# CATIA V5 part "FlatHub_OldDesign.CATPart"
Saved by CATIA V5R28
Part number: FlatHub_OldDesign
Material "Aluminium": density 2710 kg/m3, Young's modulus 7e+10 Pa, Poisson ratio 0.346, thermal expansion 2.36e-05 1/K
Bounding box of the stored display mesh (mm): x -147.037 to 147.037, y -84.892 to 169.784, z -80 to 0
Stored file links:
  H:\Maskiningenjör\Examensarbete\Klart\Klart & Skickas\FlatHub_OldDesign.CATPart
  H:\Maskiningenjör\Examensarbete\Klart\Stativ o allt\Undersida_Nav_3_alt3.CATPart
  H:\Examensarbete\Catia filer\BestNavDesigns\Nav1.3_Klar.CATPart
  H:\Maskiningenjör\Examensarbete\Klart\Klart & Skickas\AssemblyBlad_OriginalDesign.CATProduct
  H:\Maskiningenjör\Examensarbete\Klart\Klart & Skickas\HJALPMEDEL.CATPart
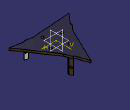
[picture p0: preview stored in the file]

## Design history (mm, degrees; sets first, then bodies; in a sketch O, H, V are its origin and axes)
Set1
  DatumPoint1 to DatumPoint4: linked copy from another document
Set2 "Design4_OriginalDesign"
  Set3 "PartUnderHub /Fills+Sketches+Extrudes+Trim"
    Set4 "Extrudes"
      Extrude1 "Extrude.ForUndersida": Element1 Sketch1, Lim1 20, Lim2 0, Direction (0, 0, 1), FirstUpto xy-plane
      Extrude2 "Extrude.SketchForLegs": Element1 Sketch3, Lim1 70, Lim2 0
      Extrude3 "Extrude.InnerMiddleTriangle": Element1 Sketch2, Lim1 30, Lim2 0
    Set5 "Fills"
      Fill1 "UnderFill": Boundary Sketch1
      Fill2 "Fill.UnderLeg1": Boundary (edge of Extrude2; edge of Extrude2; edge of Extrude2; edge of Extrude2; edge of Extrude2)
      Fill3 "Fill.UnderLeg2": Boundary (edge of Extrude2; edge of Extrude2; edge of Extrude2; edge of Extrude2; edge of Extrude2)
      Fill4 "Fill.UnderLeg3": Boundary (edge of Extrude2; edge of Extrude2; edge of Extrude2; edge of Extrude2; edge of Extrude2)
      Fill5 "Fill.UnderMiddleTriangle": Boundary (edge of Extrude3; edge of Extrude3; edge of Extrude3)
      Fill6 "TopOfUndersida.Fill": Boundary (edge of Extrude1; edge of Extrude1; edge of Extrude1; edge of Extrude1; edge of Extrude1; edge of Extrude1; edge of Extrude1; edge of Extrude1; edge of Extrude1; edge of Extrude1; edge of Extrude1; edge of Extrude1)
    Set6 "Trims"
      Trim1: Trimmed (Fill1; Extrude2)
      Trim2: Trimmed (Trim1; Extrude3)
    Set7 "JoinedUndersida"
      Join1 "Join.Undersida": Elements (Trim2; Extrude1; Fill2; Fill3; Fill4; Fill5; Fill6)
    Set8 "Sketches"
      Sketch1 "SketchForUnderSida" on Plane1, origin (0, 0, -10), H (1, 0, 0), V (0, 1, 0)
        construction line L1 (21.7487, 107.4703) -> (27.6798, 90.4756)
        construction line L2 (-103.9464, -34.9002) -> (-92.194, -21.2664)
        construction line L3 (82.1977, -72.5701) -> (64.5142, -69.2092)
        construction line L4 (-155.7574, -1.82) -> (-42.4451, -36.4864)
        construction line L5 (60.4543, -51.6084) -> (73.7984, -109.458)
        point P1 (-92.194, -21.2664)
        point P2 (27.6798, 90.4756)
        point P3 (64.5142, -69.2092)
        point P4 (0, 0)
        point P5 (21.7487, 107.4703)
        point P6 (-103.9464, -34.9002)
        point P7 (82.1977, -72.5701)
        construction line L6 (27.6798, 90.4756) -> (-92.194, -21.2664)
        construction line L7 (-92.194, -21.2664) -> (64.5142, -69.2092)
        construction line L8 (64.5142, -69.2092) -> (27.6798, 90.4756)
        construction circle A1 centre (0, 0) radius 47.3075
        line L9 (-107.7337, -31.6358) -> (-103.9464, -34.9002)
        line L10 (82.1977, -72.5701) -> (81.2642, -77.4822)
        line L11 (21.7487, 107.4703) -> (26.4695, 109.118)
        construction line L12 (27.6798, 90.4756) -> (38.5506, 74.5035)
        point P16 (147.0373, -84.892)
        line L13 (147.0373, -84.892) -> (82.1977, -72.5701)
        construction line L14 (64.5142, -69.2092) -> (45.2466, -70.6376)
        point P17 (-147.0373, -84.892)
        line L15 (-147.0373, -84.892) -> (-103.9464, -34.9002)
        line L16 (-83.7972, -3.8659) -> (0, 169.784)
        point P18 (0, 169.784)
        line L17 (0, 169.784) -> (21.7487, 107.4703)
        point P20 (-103.9464, -34.9002)
        construction line L18 (-83.7972, -3.8659) -> (-92.194, -21.2664)
        line L19 (45.2466, -70.6376) -> (-147.0373, -84.892)
        point P22 (82.1977, -72.5701)
        construction line L20 (82.1977, -72.5701) -> (64.5142, -69.2092)
        line L21 (38.5506, 74.5035) -> (147.0373, -84.892)
        point P24 (21.7487, 107.4703)
        construction line L22 (21.7487, 107.4703) -> (27.6798, 90.4756)
        point P25 (13.4514, 15.6056)
        construction line L23 (13.4514, 15.6056) -> (-20.2405, 3.8464)
        point P26 (-20.2405, 3.8464)
        construction line L24 (-20.2405, 3.8464) -> (6.7891, -19.452)
        point P27 (6.7891, -19.452)
        construction line L25 (6.7891, -19.452) -> (13.4514, 15.6056)
        construction circle A2 centre (0, 0) radius 10.3014
        construction line L26 (-92.194, -21.2664) -> (-100.3085, 31.9728)
        construction line L27 (27.6798, 90.4756) -> (71.7562, 73.2608)
        construction line L28 (64.5142, -69.2092) -> (30.3334, -96.56)
        line L29 (81.2642, -77.4822) -> (45.2466, -70.6376)
        line L30 (26.4695, 109.118) -> (38.5506, 74.5035)
        line L31 (-83.7972, -3.8659) -> (-107.7337, -31.6358)
        reference intersected line E1 through (0, 0) direction (0, 1) from yz-plane
        length L2 = 18
        length L3 = 18
        length L1 = 18
        length L25 = 35.685
        length L23 = 35.685
        length L24 = 35.685
        length L26 = 53.854
        length L27 = 47.3189
        length L28 = 43.7767
        distance P2 P25 = 76.21
        distance P26 P1 = 76.21
        distance P27 P3 = 76.21
        angle L27 L25 = 79.426
        angle L28 L13 = 130.574
        angle L26 L23 = 79.426
        angle L27 L17 = 130.574
        angle L16 L15 = 165.0003 (reference)
        angle L26 L15 = 130.574
        angle L28 L24 = 79.426
        angle L13 L19 = 165.0003 (reference)
        angle L17 L21 = 165.0003 (reference)
        distance L13 L29 = 5
        distance L17 L30 = 5
        angle L10 L13 = 90
        angle L9 L15 = 90
        distance L31 L15 = 5
        angle L17 L11 = 90
        length L8 = 163.878
        length L6 = 163.878 (reference)
        length L7 = 163.878 (reference)
        distance P17 P1 = 84
        distance P3 P16 = 84
        distance P18 P2 = 84
        distance P17 P3 = 212.132
        distance P2 P16 = 212.132
        distance P1 P18 = 212.132
        tangency: A1 L8, A1 L6, A1 L7, L4 L7, A2 L25, A2 L23, A2 L24
        coincidence: L5 L8, L14 L19, P20 P6, L21 L12, P24 P5, P7 P22, P18 E1
        parallelism: L18 L16
        concentricity: A2 O, A1 O
      Sketch2 "InnerMiddleTriangle" on Plane1, origin (0, 0, -10), H (1, 0, 0), V (0, 1, 0)
        point P1 (13.681, 15.4046)
        construction line L1 (13.681, 15.4046) -> (-20.1813, 4.1458)
        point P2 (-20.1813, 4.1458)
        construction line L2 (-20.1813, 4.1458) -> (6.5003, -19.5504)
        point P3 (6.5003, -19.5504)
        construction line L3 (6.5003, -19.5504) -> (13.681, 15.4046)
        construction circle A1 centre (0, 0) radius 10.3014
        line L4 (7.9685, 8.9724) -> (-11.7545, 2.4147)
        line L5 (-11.7545, 2.4147) -> (3.7861, -11.3871)
        line L6 (3.7861, -11.3871) -> (7.9685, 8.9724)
        construction circle A2 centre (0, 0) radius 6
        point P7 (27.6798, 90.4756)
        construction line L7 (27.6798, 90.4756) -> (-92.194, -21.2664)
        point P8 (-92.194, -21.2664)
        construction line L8 (-92.194, -21.2664) -> (64.5142, -69.2092)
        point P9 (64.5142, -69.2092)
        construction line L9 (64.5142, -69.2092) -> (27.6798, 90.4756)
        construction line L10 (27.6798, 90.4756) -> (0, 169.784)
        point P10 (0, 169.784)
        construction line L11 (0, 169.784) -> (-92.194, -21.2664)
        construction line L12 (-92.194, -21.2664) -> (-147.0373, -84.892)
        construction line L13 (-147.0373, -84.892) -> (64.5142, -69.2092)
        construction line L14 (64.5142, -69.2092) -> (147.0373, -84.892)
        construction line L15 (147.0373, -84.892) -> (27.6798, 90.4756)
        reference intersected line E1 through (0, 0) direction (0, 1) from yz-plane
        construction circle A3 centre (0, 0) radius 47.3075
        point P13 (0, 0)
        length L3 = 35.685
        length L1 = 35.685
        length L2 = 35.685
        radius A2 = 6
        distance L6 L3 = 4.3014 (reference)
        length L9 = 163.878
        length L7 = 163.878
        length L8 = 163.878
        length L15 = 212.132
        length L14 = 84
        length L13 = 212.132
        length L12 = 84
        length L11 = 212.132
        length L10 = 84
        distance P1 P7 = 76.365
        distance P9 P3 = 76.365 (reference)
        distance P2 P8 = 76.365 (reference)
        angle L10 L15 = 165 (reference)
        angle L11 L12 = 165 (reference)
        angle L13 L14 = 165 (reference)
        tangency: A1 L3, A1 L1, A1 L2, A2 L4, A2 L6, A2 L5, A3 L8, A3 L9, A3 L7
        parallelism: L4 L1, L2 L5
        coincidence: P10 E1, P13 O
      Sketch3 "SketchForLegs" on Plane1, origin (0, 0, -10), H (1, 0, 0), V (0, 1, 0)
        construction line L1 (27.6798, 90.4756) -> (42.5834, 84.6546)
        construction line L2 (21.7484, 107.4702) -> (27.6798, 90.4756)
        construction line L3 (23.7707, 86.8317) -> (80.6201, 139.8245)
        construction line L4 (-103.9462, -34.9004) -> (-92.194, -21.2664)
        construction line L5 (-92.194, -21.2664) -> (-94.6047, -5.449)
        construction line L6 (82.1977, -72.5698) -> (64.5142, -69.2092)
        construction line L7 (64.5142, -69.2092) -> (52.0214, -79.2056)
        construction line L8 (-143.1451, -5.6786) -> (-29.8328, -40.345)
        construction line L9 (50.8896, -10.1436) -> (64.2338, -67.9933)
        point P3 (65.0054, -71.3383)
        point P5 (-94.2835, -20.6271)
        point P6 (29.2781, 91.9655)
        point P7 (0, 0)
        construction line L10 (27.6798, 90.4756) -> (-92.194, -21.2664)
        construction line L11 (-92.194, -21.2664) -> (64.5142, -69.2092)
        construction line L12 (64.5142, -69.2092) -> (27.6798, 90.4756)
        construction circle A1 centre (0, 0) radius 47.3075
        point P21 (42.8347, 24.7759)
        point P22 (-40.9067, 26.5418)
        point P23 (0.0358, -49.4829)
        construction line L13 (-94.6047, -5.449) -> (-96.5515, -5.7457)
        line L14 (-94.2835, -20.6271) -> (-94.8786, -16.7226)
        line L15 (-94.2835, -20.6271) -> (-105.4611, -33.5946)
        construction line L16 (-105.4611, -33.5946) -> (-103.9462, -34.9004)
        construction line L17 (82.1977, -72.5698) -> (81.8243, -74.5346)
        line L18 (81.8243, -74.5346) -> (65.0054, -71.3383)
        line L19 (65.0054, -71.3383) -> (61.9215, -73.806)
        construction line L20 (53.2517, -80.7432) -> (52.0214, -79.2056)
        construction line L21 (21.7484, 107.4702) -> (23.6367, 108.1293)
        line L22 (29.2781, 91.9655) -> (23.6367, 108.1293)
        construction line L23 (42.5834, 84.6546) -> (43.1156, 86.0172)
        construction line L24 (43.1156, 86.0172) -> (33.0165, 90.3585)
        construction line L25 (27.6798, 90.4756) -> (147.0373, -84.892)
        construction line L26 (147.0373, -84.892) -> (64.5142, -69.2092)
        construction line L27 (64.5142, -69.2092) -> (-147.0373, -84.892)
        construction line L28 (-147.0373, -84.892) -> (-92.194, -21.2664)
        construction line L29 (-92.194, -21.2664) -> (0, 169.784)
        point P32 (0, 169.784)
        construction line L30 (0, 169.784) -> (27.6798, 90.4756)
        line L31 (23.6367, 108.1293) -> (26.4692, 109.1178)
        line L32 (26.4692, 109.1178) -> (31.6756, 94.2003)
        point P34 (31.6756, 94.2003)
        construction line L33 (31.6756, 94.2003) -> (44.2076, 88.8132)
        construction line L34 (44.2076, 88.8132) -> (43.1156, 86.0172)
        construction line L35 (-96.5515, -5.7457) -> (-99.4717, -6.1908)
        construction line L36 (-99.4717, -6.1908) -> (-97.4177, -19.6683)
        point P37 (-97.4177, -19.6683)
        line L37 (-97.4177, -19.6683) -> (-107.7334, -31.6359)
        point P38 (-107.7334, -31.6359)
        line L38 (-107.7334, -31.6359) -> (-105.4611, -33.5946)
        line L39 (81.8243, -74.5346) -> (81.2642, -77.4819)
        line L40 (81.2642, -77.4819) -> (65.742, -74.532)
        point P40 (65.742, -74.532)
        construction line L41 (65.742, -74.532) -> (55.264, -83.2581)
        construction line L42 (55.264, -83.2581) -> (53.2517, -80.7432)
        line L43 (65.742, -74.532) -> (61.9215, -73.806)
        point P42 (61.9215, -73.806)
        point P43 (61.9215, -73.806)
        construction line L44 (61.9215, -73.806) -> (53.2517, -80.7432)
        line L45 (-97.4177, -19.6683) -> (-94.8786, -16.7226)
        point P44 (-94.8786, -16.7226)
        point P45 (-94.8786, -16.7226)
        construction line L46 (-94.8786, -16.7226) -> (-96.5515, -5.7457)
        line L47 (31.6756, 94.2003) -> (33.0165, 90.3585)
        point P46 (33.0165, 90.3585)
        point P47 (33.0165, 90.3585)
        line L48 (33.0165, 90.3585) -> (29.2781, 91.9655)
        reference intersected line E1 through (0, 0) direction (0, 1) from yz-plane
        length L1 = 16
        angle L2 L1 = 130.574
        length L4 = 18
        length L5 = 16
        angle L5 L4 = 130.574
        length L6 = 18
        length L7 = 16
        angle L7 L6 = 130.574
        length L2 = 18
        distance L15 L4 = 2
        angle L21 L2 = 90
        angle L1 L23 = 90
        angle L17 L6 = 90
        angle L20 L7 = 90
        angle L4 L16 = 90
        angle L13 L5 = 90
        angle L30 L25 = 165 (reference)
        angle L29 L28 = 165 (reference)
        angle L6 L27 = 165
        angle L4 L29 = 165
        angle L2 L25 = 165
        distance L33 L24 = 3
        distance L37 L15 = 3
        distance L18 L26 = 2
        distance P3 L26 = 2 (reference)
        distance L30 L22 = 2
        distance L32 L22 = 3
        distance L40 L18 = 3
        length L28 = 84
        length L29 = 212.132
        length L30 = 84
        length L25 = 212.132
        length L26 = 84
        length L27 = 212.132
        length L12 = 163.878
        length L10 = 163.878
        length L11 = 163.878
        coincidence: P6 L3, P21 L12, P22 L10, P23 L11, P5 L8, L9 L12, L3 L10, P3 L9, P34 L3, P37 L8, P38 L16, P40 L9, P42 L19, L19 L44, L43 P43, P44 L14, L14 L46, L45 P45, P46 L24, L24 L48, L47 P47, P32 E1
        tangency: A1 L12, A1 L10, A1 L11, L8 L11
        parallelism: L14 L5, L7 L19, L31 L21, L33 L24, L35 L13, L36 L14, L39 L17, L43 L40, L45 L37, L47 L32
        perpendicularity: L34 L1, L42 L7
        concentricity: A1 O
      Sketch4 "SketchForTopFill" on xy-plane, origin (0, 0, 0), H (1, 0, 0), V (0, 1, 0)
        point P1 (27.6798, 90.4756)
        construction line L1 (27.6798, 90.4756) -> (45.3778, 83.5632)
        point P2 (45.3778, 83.5632)
        construction line L2 (21.4189, 108.4144) -> (27.6798, 90.4756)
        point P3 (-92.194, -21.2664)
        construction line L3 (-92.194, -21.2664) -> (-95.0568, -2.4833)
        point P4 (-95.0568, -2.4833)
        construction line L4 (-104.5991, -35.6579) -> (-92.194, -21.2664)
        point P5 (64.5142, -69.2092)
        construction line L5 (83.1802, -72.7565) -> (64.5142, -69.2092)
        construction line L6 (-106.705, -35.0378) -> (-94.2835, -20.6271)
        point P7 (-94.2835, -20.6271)
        construction line L7 (-94.2835, -20.6271) -> (-96.7963, -4.1395)
        construction line L8 (65.0054, -71.3383) -> (51.9831, -81.7583)
        point P9 (65.0054, -71.3383)
        construction line L9 (65.0054, -71.3383) -> (83.6962, -74.8904)
        construction line L10 (29.2781, 91.9655) -> (44.8132, 85.8979)
        point P12 (29.2781, 91.9655)
        construction line L11 (29.2781, 91.9655) -> (23.0089, 109.9282)
        construction line L12 (83.6962, -74.8904) -> (83.1802, -72.7565)
        point P15 (83.1802, -72.7565)
        construction line L13 (51.9831, -81.7583) -> (49.679, -81.0799)
        point P16 (49.679, -81.0799)
        construction line L14 (-106.705, -35.0378) -> (-104.5991, -35.6579)
        point P18 (-95.0568, -2.4833)
        construction line L15 (-95.0568, -2.4833) -> (-96.7963, -4.1395)
        construction line L16 (23.0089, 109.9282) -> (21.4189, 108.4144)
        construction line L17 (44.8132, 85.8979) -> (45.3778, 83.5632)
        point P20 (45.3778, 83.5632)
        construction line L18 (64.5142, -69.2092) -> (49.679, -81.0799)
        construction line L19 (27.6798, 90.4756) -> (-92.194, -21.2664)
        construction line L20 (-92.194, -21.2664) -> (64.5142, -69.2092)
        construction line L21 (64.5142, -69.2092) -> (27.6798, 90.4756)
        construction line L22 (64.5142, -69.2092) -> (82.1977, -72.5698)
        point P21 (147.0373, -84.892)
        line L23 (147.0373, -84.892) -> (38.5495, 74.5051)
        construction line L24 (27.6798, 90.4756) -> (21.7484, 107.4702)
        point P22 (0, 169.784)
        line L25 (0, 169.784) -> (-83.7981, -3.8677)
        construction line L26 (-92.194, -21.2664) -> (-103.9462, -34.9004)
        point P23 (-147.0373, -84.892)
        line L27 (-147.0373, -84.892) -> (45.2486, -70.6374)
        construction line L28 (27.6798, 90.4756) -> (49.1412, 110.4811)
        construction line L29 (23.0089, 109.9282) -> (-96.7963, -4.1395)
        construction line L30 (45.3778, 83.5632) -> (83.1802, -72.7565)
        construction line L31 (51.9831, -81.7583) -> (-104.5991, -35.6579)
        point P25 (46.2228, 10.088)
        construction circle A1 centre (0, 0) radius 47.3075
        point P26 (0, 0)
        line L32 (-83.7981, -3.8677) -> (-107.7334, -31.636)
        point P27 (-83.7981, -3.8677)
        line L33 (-107.7334, -31.636) -> (-103.9462, -34.9004)
        point P29 (-103.9462, -34.9004)
        point P30 (82.1977, -72.5698)
        line L34 (82.1977, -72.5698) -> (81.2642, -77.4819)
        line L35 (81.2642, -77.4819) -> (45.2486, -70.6374)
        point P32 (45.2486, -70.6374)
        point P33 (21.7484, 107.4702)
        line L36 (21.7484, 107.4702) -> (26.4692, 109.1178)
        line L37 (26.4692, 109.1178) -> (38.5495, 74.5051)
        point P35 (38.5495, 74.5051)
        point P36 (21.7484, 107.4702)
        line L38 (21.7484, 107.4702) -> (0, 169.784)
        point P37 (38.5495, 74.5051)
        construction line L39 (38.5495, 74.5051) -> (27.6798, 90.4756)
        point P38 (-103.9462, -34.9004)
        line L40 (-103.9462, -34.9004) -> (-147.0373, -84.892)
        point P39 (-83.7981, -3.8677)
        construction line L41 (-83.7981, -3.8677) -> (-92.194, -21.2664)
        point P40 (82.1977, -72.5698)
        line L42 (82.1977, -72.5698) -> (147.0373, -84.892)
        point P41 (45.2486, -70.6374)
        construction line L43 (45.2486, -70.6374) -> (64.5142, -69.2092)
        angle L2 L1 = 130.574
        angle L3 L4 = 130.574
        distance L6 L4 = 2
        distance L9 L5 = 2
        distance L2 L11 = 2
        angle L18 L5 = 130.574
        distance P15 P5 = 19
        distance P16 P5 = 19
        length L2 = 19
        length L1 = 19
        length L4 = 19
        length L3 = 19
        length L20 = 163.878
        length L19 = 163.878
        length L21 = 163.878
        radius A1 = 47.3075 (reference)
        angle L24 L23 = 165 (reference)
        length L33 = 5
        distance L35 L22 = 5
        distance L34 P5 = 18
        distance L33 P3 = 18
        distance L37 L24 = 5
        distance L36 P1 = 18
        distance P1 P22 = 84
        distance P21 P1 = 212.132
        distance P3 P23 = 84
        distance P22 P3 = 212.132
        distance P5 P21 = 84
        distance P23 P5 = 212.132
        parallelism: L7 L3, L10 L1, L18 L8, L9 L5, L32 L6, L35 L9
        coincidence: P4 P18, P20 L1, P2 P20, L5 L22, L2 L24, L28 L19, P12 L28, P9 L21, P7 L20, L15 L29, L16 L29, L17 L30, L12 L30, L13 L31, L14 L31, L4 L26, P25 L21, P22 V, P26 O, P27 L25, P29 L26, P30 L22, P32 L27, P33 L24, P35 L23, L24 L38, L36 P36, L23 L39, L37 P37, L26 L40, L33 P38, L25 L41, L32 P39, L22 L42, L34 P40, L27 L43, L35 P41
        tangency: A1 L20, A1 L21, A1 L19
        perpendicularity: L33 L26, L34 L9, L36 L11
  Set9 "Planes"
    Plane1 "Plane.Under": type Offset, RefPlane xy-plane, Offset 10, reversed
Body1 (main body), material "Aluminium"
  CloseSurface1: CloseElement Join1
  Sketch5 on face of CloseSurface1, origin (26.3136, 100.4596, -43.2148), H (0.3295, -0.9441, 0), V (0, 0, 1)
    point P1 (0, -4.7852)
    reference projected line E1 (62.2148, 33.2148) -> (-74.1234, 33.2148) from edge [face of CloseSurface1 | face of CloseSurface1]
    distance E1 P1 = 38
  Hole1: placed by Sketch5, at (26.3136, 100.4596, -48) direction (0.9441, 0.3295, 0), diameter 10, depth 10, V-bottom angle 120
  Sketch6 on face of CloseSurface1, origin (-101.8716, -24.8355, -49.7767), H (0.6529, 0.7574, 0), V (0, 0, -1)
    point P1 (0, -1.7767)
    reference projected line E1 (-74.9782, -39.7767) -> (-8.9782, -39.7767) from edge [face of CloseSurface1 | face of CloseSurface1]
    distance E1 P1 = 38
  Hole2: placed by Sketch6, at (-101.8716, -24.8355, -48) direction (0.7574, -0.6529, 0), diameter 10, depth 10, V-bottom angle 120
  Sketch7 on face of CloseSurface1, origin (74.1774, -76.1351, -48.0407), H (0.9824, -0.1867, 0), V (0, 0, 1)
    point P1 (0, 0.0407)
    reference projected line E1 (73.2137, 38.0407) -> (7.2137, 38.0407) from edge [face of CloseSurface1 | face of CloseSurface1]
    distance E1 P1 = 38
  Hole3: placed by Sketch7, at (74.1774, -76.1351, -48) direction (0.1867, 0.9824, 0), diameter 10, depth 10, V-bottom angle 120
  Sketch8, origin (-46.9718, -19.2982, 0), H (1, 0, 0), V (0, 1, 0), geometry linked from another document
  Hole4: placed by Sketch8, at (-46.9718, -19.2982, 0) direction (0, 0, -1), diameter 12, through (limit type 3)
  Sketch9, origin (-19.1171, 47.0954, 0), H (1, 0, 0), V (0, 1, 0), geometry linked from another document
  Hole5: placed by Sketch9, at (-19.1171, 47.0954, 0) direction (0, 0, -1), diameter 12, through (limit type 3)
  Sketch10, origin (47.2765, 19.2407, 0), H (1, 0, 0), V (0, 1, 0), geometry linked from another document
  Hole6: placed by Sketch10, at (47.2765, 19.2407, 0) direction (0, 0, -1), diameter 12, through (limit type 3)
  Sketch11, origin (19.4218, -47.153, 0), H (1, 0, 0), V (0, 1, 0), geometry linked from another document
  Hole7: placed by Sketch11, at (19.4218, -47.153, 0) direction (0, 0, -1), diameter 12, through (limit type 3)
  Sketch12 on face of CloseSurface1, origin (0, 0, 0), H (1, 0, 0), V (0, 1, 0)
    axis line L1 (0, 169.784) -> (0, 0)
    point P1 (0, 169.784)
    point P2 (0, 0)
    reference projected point E1 (0, 169.784) from vertex [face of CloseSurface1 | face of CloseSurface1 | face of CloseSurface1]
    length L1 = 169.784 (reference)
    coincidence: P1 V, P1 E1, P2 H
    vertical: L1 V
  Sketch13 "Positioning sketch - Assembly Hole.5" on face of CloseSurface1, origin (-46.9718, -19.2982, 0), H (1, 0, 0), V (0, 1, 0)
    point P1 (0, 0)
    reference projected point E1 (0, 0) from vertex of DatumPoint1
    coincidence: E1 P1
  Sketch14 "Positioning sketch - Assembly Hole.6" on face of CloseSurface1, origin (-19.1171, 47.0954, 0), H (1, 0, 0), V (0, 1, 0)
    point P1 (0, 0)
    reference projected point E1 (0, 0) from vertex of DatumPoint2
    coincidence: E1 P1
  Sketch15 "Positioning sketch - Assembly Hole.7" on face of CloseSurface1, origin (47.2765, 19.2407, 0), H (1, 0, 0), V (0, 1, 0)
    point P1 (0, 0)
    reference projected point E1 (0, 0) from vertex of DatumPoint3
    coincidence: E1 P1
  Sketch16 "Positioning sketch - Assembly Hole.8" on face of CloseSurface1, origin (19.4218, -47.153, 0), H (1, 0, 0), V (0, 1, 0)
    point P1 (0, 0)
    reference projected point E1 (0, 0) from vertex of DatumPoint4
    coincidence: E1 P1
